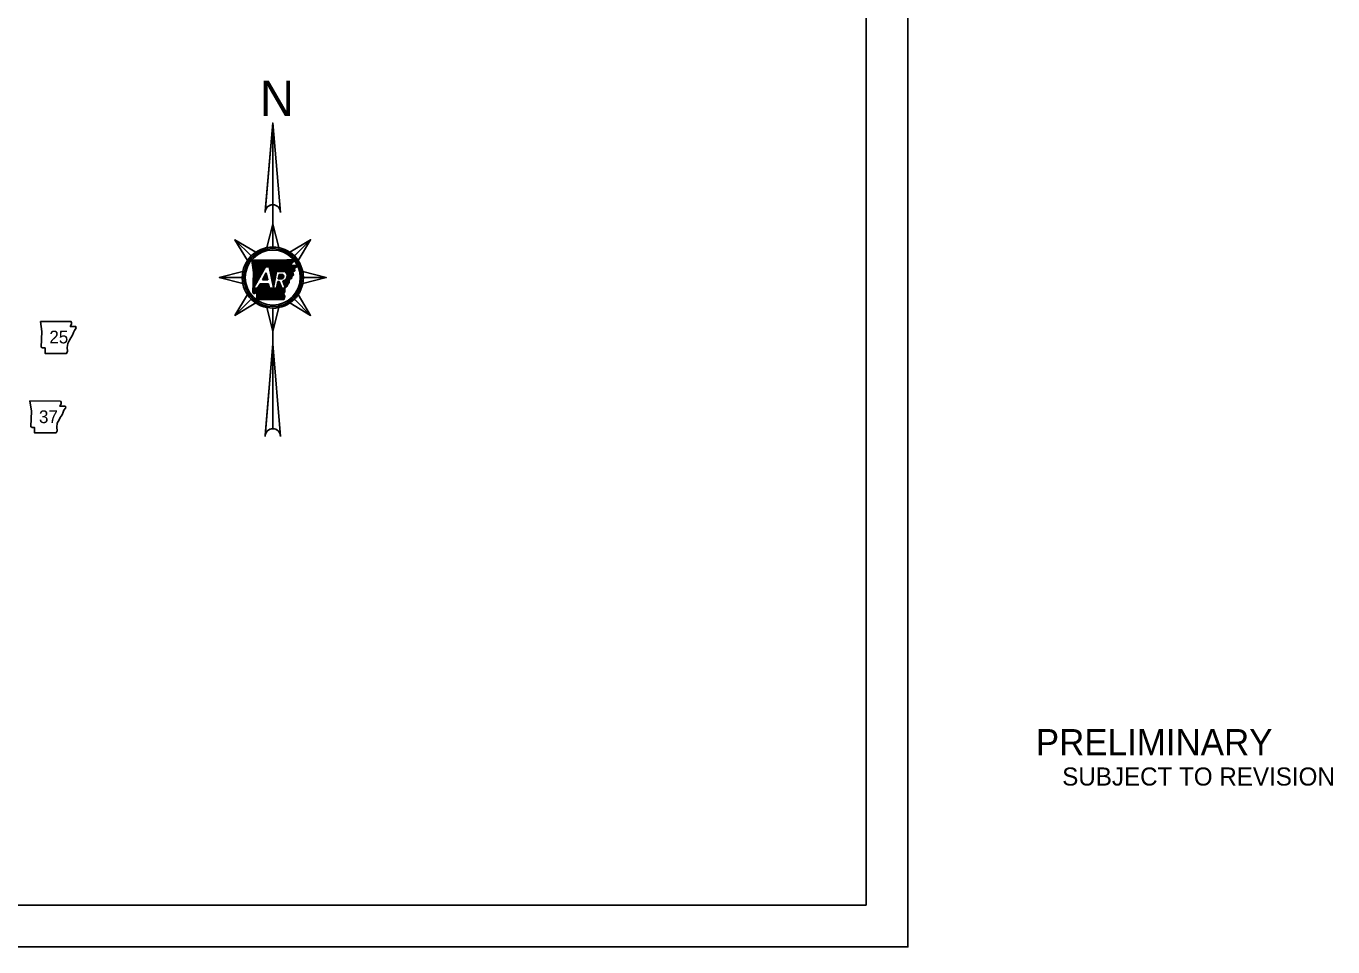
# Model space of a CAD drawing. Extents: x 840176 to 859715, y 1589036 to 1600368.
# Drawn here: x 851907 to 859715, y 1589036 to 1594536 of the extents above; entities that cross this region are included whole.
import ezdxf

# ---------------------------------------------------------------- set-up
doc = ezdxf.new("R2010")
doc.units = 0
for name, color, linetype in [('2', 7, 'Continuous'), ('DSN_DRFT_Border', 7, 'Continuous'), ('SHET_Border-Text', 7, 'Continuous'), ('SHET_Stamp-Prelim', 7, 'Continuous')]:
    doc.layers.add(name, color=color, linetype=linetype)

msp = doc.modelspace()

# ---------------------------------------------------------------- linework, layer by layer
at = {"layer": '2'}
for points in [[(851992.4, 1592771.9), (852001.6, 1592711), (851997.5, 1592618.7), (852005.6, 1592613.6), (852020.8, 1592613.6), (852020.8, 1592581.1), (852148.7, 1592581.1), (852154.8, 1592594.3), (852152.8, 1592615.6), (852155.8, 1592640), (852167, 1592659.3), (852174.1, 1592673.5), (852184.3, 1592688.7), (852190.4, 1592704.9), (852195.4, 1592718.1), (852204.6, 1592729.3), (852206.6, 1592736.4), (852202.5, 1592741.5), (852171.1, 1592741.5), (852178.2, 1592755.7), (852179.2, 1592764.8), (852175, 1592771.9)], [(851929.8, 1592296.4), (851938.9, 1592235.5), (851934.9, 1592143.1), (851943, 1592138), (851958.2, 1592138), (851958.2, 1592105.5), (852086.1, 1592105.5), (852092.2, 1592118.7), (852090.2, 1592140), (852093.2, 1592164.4), (852104.4, 1592183.7), (852111.5, 1592197.9), (852121.6, 1592213.1), (852127.7, 1592229.4), (852132.8, 1592242.6), (852141.9, 1592253.7), (852144, 1592260.8), (852139.9, 1592265.9), (852108.4, 1592265.9), (852115.6, 1592280.1), (852116.6, 1592289.3), (852112.4, 1592296.3)]]:
    msp.add_lwpolyline(points, close=True, dxfattribs=at)
at = {"layer": 'DSN_DRFT_Border'}
for p, q in [((853381.1, 1593957.3), (853336.1, 1593430.8)), ((853381.1, 1593957.3), (853381.1, 1593236.2)), ((853381.1, 1593468.7), (853381.1, 1593957.3)), ((853336.8, 1593438.1), (853338.8, 1593440.2)), ((853337, 1593441), (853341.2, 1593445.1)), ((853381.1, 1593353.3), (853345.6, 1593212.8)), ((853381.1, 1593216.3), (853381.1, 1593353.3)), ((853155.1, 1593259.7), (853252, 1593162.8)), ((853252, 1593162.8), (853155.1, 1593259.7)), ((853155.1, 1593259.7), (853229.3, 1593135.2)), ((853607.2, 1593259.7), (853482.7, 1593185.5)), ((853510.3, 1593162.8), (853607.2, 1593259.7)), ((853510.3, 1593162.8), (853607.2, 1593259.7)), ((853256.6, 1593136.6), (853258.3, 1593138.2)), ((853257.2, 1593132), (853263.4, 1593138.2)), ((853257.8, 1593127.4), (853268.6, 1593138.2)), ((853258.4, 1593122.8), (853273.7, 1593138.2)), ((853258.9, 1593118.2), (853278.9, 1593138.2)), ((853259.5, 1593113.6), (853284.1, 1593138.2)), ((853260.1, 1593109), (853289.2, 1593138.2)), ((853260.7, 1593104.4), (853294.4, 1593138.2)), ((853261.2, 1593099.8), (853299.6, 1593138.2)), ((853261.8, 1593095.2), (853304.7, 1593138.2)), ((853262.4, 1593090.6), (853309.9, 1593138.2)), ((853262.9, 1593086), (853315.1, 1593138.2)), ((853263.5, 1593081.5), (853320.2, 1593138.2)), ((853264.1, 1593076.9), (853325.4, 1593138.2)), ((853264.1, 1593020), (853333.8, 1593089.7)), ((853264.3, 1593025.4), (853377.1, 1593138.3)), ((853264.4, 1593030.7), (853372, 1593138.2)), ((853264.6, 1593036.1), (853366.8, 1593138.2)), ((853264.7, 1593072.3), (853330.5, 1593138.2)), ((853264.8, 1593041.4), (853361.6, 1593138.2)), ((853265, 1593046.7), (853356.4, 1593138.2)), ((853265.1, 1593052.1), (853351.3, 1593138.2)), ((853265.2, 1593067.7), (853335.7, 1593138.2)), ((853265.3, 1593057.4), (853346.1, 1593138.2)), ((853265.5, 1593062.8), (853340.9, 1593138.2)), ((853265.8, 1592969.7), (853337.9, 1593096.9)), ((853337.9, 1593096.9), (853359.3, 1593096.9)), ((853341, 1593096.9), (853382.3, 1593138.3)), ((853346.1, 1593096.9), (853387.5, 1593138.3)), ((853351.3, 1593096.9), (853392.7, 1593138.3)), ((853356.5, 1593096.9), (853398, 1593138.4)), ((853359.7, 1593095), (853403.2, 1593138.5)), ((853360.6, 1593090.7), (853408.4, 1593138.6)), ((853361.5, 1593086.5), (853413.7, 1593138.6)), ((853362.4, 1593082.2), (853418.9, 1593138.7)), ((853363.3, 1593078), (853424.2, 1593138.8)), ((853364.2, 1593073.7), (853429.4, 1593138.9)), ((853365.2, 1593069.4), (853434.7, 1593139)), ((853366.1, 1593065.2), (853439.9, 1593139.1)), ((853367, 1593060.9), (853445.2, 1593139.1)), ((853367.9, 1593056.7), (853450.4, 1593139.2)), ((853368.8, 1593052.4), (853455.7, 1593139.3)), ((853369.7, 1593048.2), (853460.9, 1593139.4)), ((853370.6, 1593043.9), (853466.2, 1593139.5)), ((853371.5, 1593039.7), (853471.5, 1593139.6)), ((853407.4, 1593070.4), (853476.8, 1593139.7)), ((853412.6, 1593070.4), (853482.1, 1593139.8)), ((853417.8, 1593070.4), (853487.3, 1593140)), ((853422.9, 1593070.4), (853492.6, 1593140.1)), ((853428.1, 1593070.4), (853497.9, 1593140.2)), ((853433.2, 1593070.4), (853499.1, 1593136.2)), ((853438.4, 1593070.4), (853501.6, 1593133.5)), ((853443.6, 1593070.4), (853502.2, 1593129)), ((853448.7, 1593070.4), (853490.4, 1593112.1)), ((853453.4, 1593069.9), (853489.4, 1593105.9)), ((853456.3, 1593067.6), (853494.9, 1593106.2)), ((853458.8, 1593064.9), (853500.3, 1593106.4)), ((853461, 1593062), (853505.8, 1593106.7)), ((853462.9, 1593058.7), (853511.2, 1593107)), ((853464.5, 1593055.1), (853516.7, 1593107.3)), ((853465.3, 1593035.3), (853512.2, 1593082.2)), ((853465.7, 1593051.2), (853521.6, 1593107)), ((853466.4, 1593046.7), (853524, 1593104.3)), ((853466.4, 1593041.6), (853511.6, 1593086.8)), ((853521.7, 1593096.8), (853526.4, 1593101.5)), ((853061.5, 1593033.6), (853198.5, 1593033.6)), ((853198.5, 1593033.6), (853061.5, 1593033.6)), ((853061.5, 1593033.6), (853202, 1592998.1)), ((853262.8, 1592982.6), (853286.6, 1593006.4)), ((853263, 1592988), (853293.3, 1593018.3)), ((853263.2, 1592993.3), (853300.1, 1593030.2)), ((853263.4, 1592998.7), (853306.8, 1593042.1)), ((853263.5, 1593004), (853313.6, 1593054)), ((853263.7, 1593009.3), (853320.3, 1593065.9)), ((853263.9, 1593014.7), (853327, 1593077.8)), ((853318.8, 1593019.6), (853342.4, 1593061.2)), ((853318.8, 1593019.6), (853351.3, 1593019.6)), ((853319.1, 1593019.6), (853345.6, 1593046.2)), ((853324.2, 1593019.6), (853346.5, 1593041.9)), ((853325.2, 1593030.9), (853344.7, 1593050.4)), ((853329.4, 1593019.6), (853347.4, 1593037.6)), ((853332, 1593042.9), (853343.8, 1593054.7)), ((853334.6, 1593019.6), (853348.3, 1593033.4)), ((853338.7, 1593054.8), (853342.9, 1593058.9)), ((853339.7, 1593019.6), (853349.2, 1593029.1)), ((853344.9, 1593019.6), (853350.2, 1593024.9)), ((853350.1, 1593019.6), (853351.1, 1593020.6)), ((853372.4, 1593035.4), (853401.8, 1593064.7)), ((853373.4, 1593031.1), (853400.7, 1593058.5)), ((853374.3, 1593026.9), (853399.6, 1593052.2)), ((853375.2, 1593022.6), (853398.5, 1593045.9)), ((853376.1, 1593018.4), (853397.4, 1593039.7)), ((853377, 1593014.1), (853396.3, 1593033.4)), ((853377.9, 1593009.9), (853395.2, 1593027.2)), ((853378.8, 1593005.6), (853394.1, 1593020.9)), ((853379.7, 1593001.4), (853393, 1593014.7)), ((853380.6, 1592997.1), (853391.9, 1593008.4)), ((853381.5, 1592992.8), (853390.9, 1593002.1)), ((853402.7, 1593070.4), (853452.8, 1593070.4)), ((853407, 1592987.3), (853422.4, 1593002.7)), ((853408.1, 1592993.5), (853421, 1593006.5)), ((853409.2, 1592999.8), (853419.5, 1593010.1)), ((853410.3, 1593006.1), (853414.3, 1593010.1)), ((853419.6, 1593010.1), (853411, 1593010.1)), ((853413.6, 1593025.2), (853440.8, 1593052.4)), ((853413.6, 1593025.2), (853435.1, 1593025.2)), ((853414.7, 1593031.5), (853435.6, 1593052.4)), ((853415.8, 1593037.7), (853430.5, 1593052.4)), ((853416.9, 1593044), (853425.3, 1593052.4)), ((853418, 1593050.2), (853420.1, 1593052.4)), ((853418.3, 1593052.4), (853441.8, 1593052.4)), ((853418.8, 1593025.2), (853443.7, 1593050.1)), ((853434.6, 1592969.7), (853419.6, 1593010.1)), ((853424, 1593025.2), (853445.4, 1593046.7)), ((853429.1, 1593025.2), (853446.4, 1593042.5)), ((853434.3, 1593025.2), (853446, 1593036.9)), ((853440.8, 1593012.3), (853456.6, 1592969.7)), ((853441.2, 1593011.2), (853442.8, 1593012.8)), ((853442.6, 1593007.4), (853452.5, 1593017.3)), ((853444, 1593003.7), (853501.3, 1593060.9)), ((853445.4, 1592999.9), (853502.3, 1593056.7)), ((853446.8, 1592996.1), (853503.2, 1593052.5)), ((853448.2, 1592992.3), (853504.2, 1593048.3)), ((853449.6, 1592988.6), (853480.6, 1593019.6)), ((853451, 1592984.8), (853480, 1593013.8)), ((853452.4, 1592981), (853479.4, 1593008.1)), ((853460.9, 1593025.7), (853500.3, 1593065.1)), ((853486.5, 1593025.5), (853493.8, 1593032.7)), ((853506.5, 1593071.3), (853512.8, 1593077.6)), ((853700.8, 1593033.6), (853560.3, 1593069.2)), ((853563.8, 1593033.6), (853700.8, 1593033.6)), ((853563.8, 1593033.6), (853700.8, 1593033.6)), ((853261.7, 1592945.3), (853286, 1592969.7)), ((853261.8, 1592950.6), (853280.9, 1592969.7)), ((853262, 1592955.9), (853275.7, 1592969.7)), ((853262.1, 1592961.3), (853270.5, 1592969.7)), ((853262.3, 1592966.6), (853266.4, 1592970.6)), ((853262.5, 1592971.9), (853273.1, 1592982.5)), ((853262.7, 1592977.3), (853279.8, 1592994.5)), ((853263.6, 1592942.1), (853317.9, 1592996.4)), ((853290.5, 1592969.7), (853265.8, 1592969.7)), ((853266.7, 1592940), (853323.1, 1592996.4)), ((853270.4, 1592938.5), (853328.2, 1592996.4)), ((853276.5, 1592939.5), (853333.4, 1592996.4)), ((853281.8, 1592939.6), (853338.6, 1592996.4)), ((853285.8, 1592938.4), (853343.7, 1592996.4)), ((853286, 1592928.3), (853354.1, 1592996.4)), ((853286, 1592933.4), (853348.9, 1592996.4)), ((853286, 1592923.1), (853356.8, 1592993.9)), ((853286, 1592918), (853357.7, 1592989.7)), ((853286, 1592912.8), (853358.6, 1592985.4)), ((853286.1, 1592907.7), (853359.5, 1592981.1)), ((853286.1, 1592902.6), (853360.4, 1592976.9)), ((853305.6, 1592996.4), (853290.5, 1592969.7)), ((853291.3, 1592902.6), (853361.3, 1592972.6)), ((853296.4, 1592980), (853312.7, 1592996.4)), ((853296.5, 1592902.6), (853363.5, 1592969.7)), ((853301.6, 1592902.6), (853368.7, 1592969.7)), ((853303.1, 1592991.9), (853307.6, 1592996.4)), ((853356.3, 1592996.4), (853305.6, 1592996.4)), ((853306.8, 1592902.6), (853373.9, 1592969.7)), ((853311.9, 1592902.6), (853379, 1592969.7)), ((853317.1, 1592902.6), (853384.2, 1592969.7)), ((853322.2, 1592902.5), (853389.4, 1592969.7)), ((853327.4, 1592902.5), (853394.5, 1592969.7)), ((853332.6, 1592902.5), (853399.7, 1592969.7)), ((853337.7, 1592902.5), (853426.6, 1592991.4)), ((853342.9, 1592902.5), (853428, 1592987.6)), ((853348, 1592902.5), (853429.4, 1592983.8)), ((853353.2, 1592902.5), (853430.8, 1592980.1)), ((853358.3, 1592902.5), (853432.1, 1592976.3)), ((853403.9, 1592969.7), (853362, 1592969.7)), ((853363.5, 1592902.5), (853433.5, 1592972.5)), ((853368.7, 1592902.5), (853435.8, 1592969.7)), ((853373.8, 1592902.5), (853441, 1592969.7)), ((853379, 1592902.5), (853446.2, 1592969.7)), ((853382.5, 1592988.6), (853389.8, 1592995.9)), ((853383.4, 1592984.3), (853388.7, 1592989.6)), ((853384.1, 1592902.4), (853451.3, 1592969.7)), ((853384.3, 1592980.1), (853387.6, 1592983.4)), ((853385.2, 1592975.8), (853386.5, 1592977.1)), ((853389.3, 1592902.4), (853453.1, 1592966.2)), ((853394.5, 1592902.4), (853453.3, 1592961.3)), ((853399.6, 1592902.4), (853453.5, 1592956.3)), ((853404.8, 1592974.8), (853425.2, 1592995.1)), ((853404.8, 1592902.4), (853453.8, 1592951.4)), ((853405.9, 1592981), (853423.8, 1592998.9)), ((853409.9, 1592902.4), (853445.3, 1592937.8)), ((853415.1, 1592902.4), (853446.9, 1592934.2)), ((853420.2, 1592902.4), (853448.5, 1592930.6)), ((853425.4, 1592902.4), (853450.1, 1592927)), ((853456.6, 1592969.7), (853434.6, 1592969.7)), ((853453.8, 1592977.2), (853469.6, 1592993.1)), ((853455.2, 1592973.5), (853467.4, 1592985.7)), ((853607.2, 1592807.6), (853533, 1592932.1)), ((853155.1, 1592807.6), (853252, 1592904.5)), ((853252, 1592904.5), (853155.1, 1592807.6)), ((853155.1, 1592807.6), (853279.6, 1592881.8)), ((853381.1, 1592714), (853416.7, 1592854.5)), ((853381.1, 1592851), (853381.1, 1592851)), ((853381.1, 1592851), (853381.1, 1592266.3)), ((853381.1, 1592851), (853381.1, 1592714)), ((853430.6, 1592902.4), (853451.7, 1592923.5)), ((853435.7, 1592902.4), (853453, 1592919.6)), ((853440.9, 1592902.4), (853450.7, 1592912.1)), ((853446, 1592902.3), (853448.3, 1592904.6)), ((853510.3, 1592904.5), (853607.2, 1592807.6)), ((853510.3, 1592904.5), (853607.2, 1592807.6)), ((853381.1, 1592637.7), (853336.1, 1592092.6)), ((853381.1, 1592130.8), (853381.1, 1592637.7))]:
    msp.add_line(p, q, dxfattribs=at)
msp.add_lwpolyline([(840175.5, 1600035.6), (840175.5, 1589035.6), (857175.5, 1589035.6), (857175.5, 1600035.6)], close=True, dxfattribs=at)
for points in [[(853426.8, 1593423), (853381.1, 1593957.3), (853335.5, 1593423)], [(853345.6, 1593212.8), (853381.1, 1593353.3), (853416.7, 1593212.8)], [(853229.3, 1593135.2), (853155.1, 1593259.7), (853279.6, 1593185.5)], [(853482.7, 1593185.5), (853607.2, 1593259.7), (853533, 1593135.2)], [(853256.4, 1593138.2), (853327.7, 1593138.1), (853390.3, 1593138.3), (853464, 1593139.4), (853498.3, 1593140.2)], [(853261.6, 1592945.4), (853265.6, 1593064.9), (853256.4, 1593138.2)], [(853359.3, 1593096.9), (853385.8, 1592973.1), (853402.7, 1593070.4)], [(853520.6, 1593107.5), (853526.8, 1593101), (853511.4, 1593088.4), (853513.1, 1593075.6), (853499.9, 1593066.9), (853504.4, 1593047.3), (853494.3, 1593038), (853493.3, 1593028), (853481, 1593023.5), (853479.1, 1593004.5), (853470.2, 1592995), (853465.9, 1592980.6), (853453, 1592968.8), (853453.9, 1592947.9), (853445.1, 1592938.1), (853453.2, 1592920.1), (853447.6, 1592902.3)], [(853487.7, 1593105.8), (853521.1, 1593107.5)], [(853202, 1592998.1), (853061.5, 1593033.6), (853202, 1593069.2)], [(853342.4, 1593061.2), (853351.3, 1593019.6)], [(853411, 1593010.1), (853403.9, 1592969.7)], [(853413.6, 1593025.2), (853418.3, 1593052.4)], [(853560.3, 1593069.2), (853700.8, 1593033.6), (853560.3, 1592998.1)], [(853279.6, 1592881.8), (853155.1, 1592807.6), (853229.3, 1592932.1)], [(853447.6, 1592902.3), (853286.1, 1592902.6), (853286, 1592938.3)], [(853362, 1592969.7), (853356.3, 1592996.4)], [(853533, 1592932.1), (853607.2, 1592807.6), (853482.7, 1592881.8)], [(853416.7, 1592854.5), (853381.1, 1592714), (853345.6, 1592854.5)], [(853426.8, 1592085.1), (853381.1, 1592637.7), (853335.5, 1592085.1)]]:
    msp.add_lwpolyline(points, dxfattribs=at)
for radius in [182.6, 173.5, 164.4]:
    msp.add_circle((853381.1, 1593033.6), radius, dxfattribs=at)
for centre, radius, start, end in [((853381.1, 1593423), 45.7, 0, 180), ((853381.1, 1593423), 45.7, 90, 170.22959), ((853381.1, 1593033.6), 182.6, 135, 146.22909), ((853381.1, 1593033.6), 182.6, 90, 101.22909), ((853381.1, 1593033.6), 182.6, 45, 56.22909), ((853381.1, 1593033.6), 182.6, 180, 191.22909), ((853429.9, 1593040.9), 16.5, 288.12683, 43.89016), ((853434.2, 1593043.9), 32.3, 281.86262, 54.87052), ((853381.1, 1593033.6), 182.6, 0, 11.22909), ((853381.1, 1593033.6), 182.6, 315, 326.22909), ((853381.1, 1593033.6), 182.6, 225, 236.22909), ((853381.1, 1593033.6), 182.6, 270, 281.22909), ((853381.1, 1592085.1), 45.7, 0, 180), ((853381.1, 1592085.1), 45.7, 90, 170.5511)]:
    msp.add_arc(centre, radius, start, end, dxfattribs=at)
for points in [[(853498.3, 1593140.2), (853498.5, 1593138.3), (853499.1, 1593137.3), (853499.2, 1593135.4), (853499.9, 1593134.6), (853501.2, 1593133.8), (853502.4, 1593132.6), (853502.6, 1593131.1), (853502.3, 1593129.5), (853502.2, 1593127.8), (853502, 1593126.3), (853501.7, 1593124.9), (853500.7, 1593123.8), (853499.7, 1593123), (853498.7, 1593122.1), (853498.1, 1593121.1), (853496.9, 1593120.1), (853495.8, 1593119), (853494.9, 1593118), (853493.9, 1593116.8), (853493.5, 1593115.4), (853492.5, 1593114.4), (853491.7, 1593113.6), (853490.6, 1593112.4), (853490.1, 1593111.2), (853489.1, 1593109.8), (853488.9, 1593108.5), (853488.2, 1593107.4), (853488.2, 1593107.3)], [(853286, 1592938.3), (853286.2, 1592938.2), (853285.3, 1592938.7), (853284.2, 1592939.3), (853282.9, 1592939.4), (853281.3, 1592939.6), (853279.9, 1592939.8), (853278.5, 1592940.7), (853277, 1592939.7), (853275.3, 1592939), (853274.3, 1592939.8), (853273.1, 1592939.3), (853272.2, 1592939.5), (853270.6, 1592938.5), (853269.2, 1592938.9), (853268.1, 1592938.6), (853266.8, 1592938.6), (853266.5, 1592940.1), (853265.3, 1592940.3), (853264.2, 1592941), (853263.4, 1592942.5), (853262.9, 1592943.7), (853261.6, 1592945.4)]]:
    msp.add_spline(points, degree=3, dxfattribs=at)
at = {"layer": 'SHET_Border-Text'}
for points in [[(840175.5, 1589035.6), (857175.5, 1589035.6), (857175.5, 1600035.6), (840175.5, 1600035.6)], [(840425.5, 1589285.6), (856925.5, 1589285.6), (856925.5, 1599785.6), (840425.5, 1599785.6)]]:
    msp.add_lwpolyline(points, close=True, dxfattribs=at)

# ---------------------------------------------------------------- texts
at = {"layer": '2'}
for s, p in [('25', (852045.8, 1592640.4)), ('37', (851983.9, 1592164.3))]:
    msp.add_text(s, height=76.03, dxfattribs=at).set_placement(p)
at = {"layer": 'DSN_DRFT_Border'}
for s, height, p in [('N', 210.8, (853304.1, 1593998.8)), ('DWB 7-27-17', 3.552, (853370, 1592866.2))]:
    msp.add_text(s, height=height, dxfattribs=at).set_placement(p)
at = {"layer": 'SHET_Stamp-Prelim'}
for s, height, p in [('PRELIMINARY', 156, (857940.1, 1590180.5)), ('SUBJECT TO REVISION', 108, (858097.8, 1589999.1))]:
    msp.add_text(s, height=height, dxfattribs=at).set_placement(p)

doc.saveas('drawing.dxf')
